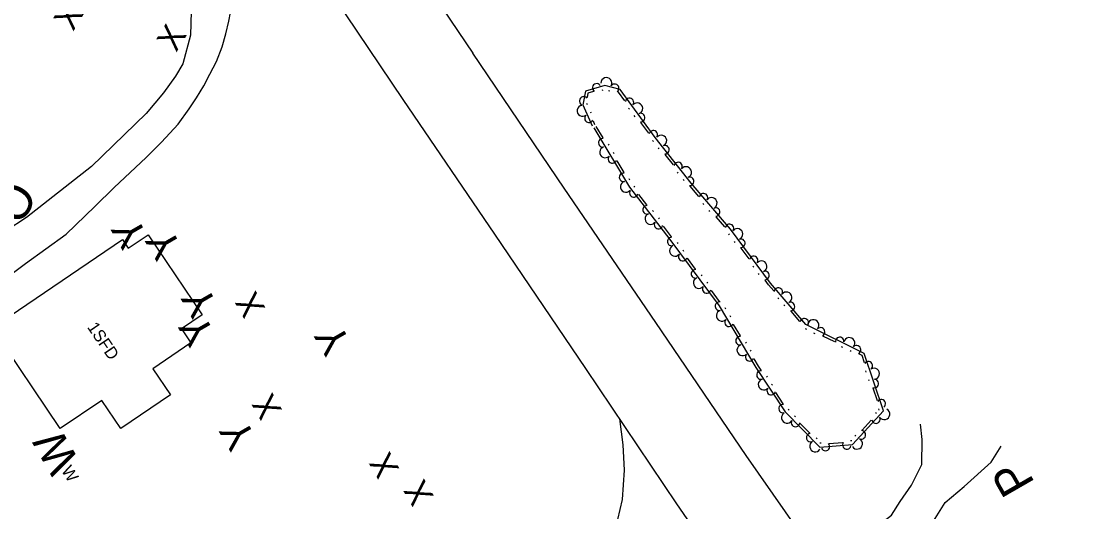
# Model space of a CAD drawing. Extents: x 2030130 to 2036320, y 723205 to 762423.
# Drawn here: x 2034222.4 to 2034546.3, y 759693.3 to 759843.4 of the extents above; entities that cross this region are included whole.
import ezdxf

# ---------------------------------------------------------------- set-up
doc = ezdxf.new("R2010")
doc.units = 0
for name, color, linetype in [('Draft_Station Cardinal Points', 7, 'Continuous'), ('Draft_Station Labels Major', 7, 'Continuous'), ('Draft_Station Tics Major', 7, 'Continuous'), ('Exist Terrain Model Ground Surface', 7, 'Continuous'), ('Old_Level_28', 7, 'Continuous'), ('Prop Horizontal Alignment Ramp', 7, 'Continuous')]:
    doc.layers.add(name, color=color, linetype=linetype)

msp = doc.modelspace()

# ---------------------------------------------------------------- linework, layer by layer
at = {"layer": 'Draft_Station Labels Major'}
for p, q in [((2034332.4, 759875.51), (2034360.74, 759833.62)), ((2034311.52, 759860.74), (2034339.29, 759819.51))]:
    msp.add_line(p, q, dxfattribs=at)
for points in [[(2034177, 759721.53), (2034180.72, 759730), (2034182.43, 759733.06), (2034184.49, 759735.91), (2034187.7, 759739.54), (2034191.49, 759743.09), (2034202.52, 759753.47), (2034223.72, 759769.25), (2034236.14, 759778.23), (2034244.9, 759786.68), (2034250.83, 759792.5), (2034255.75, 759797.17), (2034260.67, 759801.7), (2034265.36, 759806.38), (2034270.5, 759811.9), (2034273.88, 759816.63), (2034276.11, 759819.93), (2034278.35, 759823.61), (2034280.21, 759827.21), (2034282.23, 759831.05), (2034283.96, 759835.6), (2034285.09, 759839.52), (2034285.94, 759843.41), (2034287.05, 759848.7)], [(2034274.52, 759850.16), (2034274.27, 759839.19), (2034271.93, 759830.41), (2034269.69, 759826.59), (2034265.94, 759821.49), (2034260.7, 759815.17), (2034243.93, 759798.91), (2034223.99, 759783.37), (2034217.84, 759779.25), (2034213.65, 759777.27), (2034208.46, 759775.2), (2034203.67, 759773.55), (2034199.86, 759772.16), (2034197.07, 759771.63), (2034194.93, 759771.4)], [(2034673.1, 759374.03), (2034641.13, 759420.91), (2034612.37, 759462.99), (2034584.85, 759503.64), (2034556.5, 759545.4), (2034528.56, 759586.42), (2034500.61, 759627.72), (2034473.04, 759669.67), (2034444.47, 759710.51), (2034416.72, 759751.28), (2034388.73, 759792.32), (2034360.74, 759833.62)], [(2034339.29, 759819.51), (2034367.32, 759778.28), (2034395.22, 759737.17), (2034423.09, 759695.79), (2034451.3, 759654.89), (2034478.88, 759613.26), (2034507.24, 759572.41), (2034535.18, 759531.29), (2034563.29, 759490.2), (2034591.25, 759449.01), (2034619.59, 759406.87), (2034651.36, 759359.7)], [(2034405.64, 759721.71), (2034406.6, 759713.82), (2034407.01, 759706.02), (2034406.4, 759697.05), (2034404.29, 759687.94)], [(2034461.93, 759685.55), (2034467.45, 759684.39), (2034470.48, 759684.34), (2034473.71, 759684.94), (2034476.94, 759685.54), (2034481.54, 759687.19), (2034485.39, 759689.48), (2034488.94, 759692.26), (2034491.58, 759696.47), (2034495.1, 759701.46), (2034498.26, 759707.8), (2034498.3, 759715.39), (2034497.82, 759720.13)], [(2034487.48, 759647.7), (2034485.78, 759656.85), (2034486.54, 759661.62), (2034488.93, 759667.03), (2034491.55, 759672.71), (2034496.14, 759679.63), (2034499.28, 759686.35), (2034505.38, 759696.13), (2034511.18, 759701.05), (2034519.44, 759708.47), (2034522.54, 759713.39)]]:
    msp.add_lwpolyline(points, dxfattribs=at)
at = {"layer": 'Draft_Station Tics Major'}
for points in [[(2034397.73, 759810.77), (2034408.7, 759792.6), (2034421.07, 759776.67), (2034436.15, 759756.32), (2034447.41, 759737.48), (2034456.37, 759723.85), (2034466.95, 759713.13), (2034477.01, 759713.94), (2034486.52, 759724.21), (2034480.57, 759741.76), (2034462.71, 759750.6), (2034451.91, 759763.31), (2034439.58, 759779.74), (2034427.57, 759793.85), (2034416.59, 759807.85), (2034405.79, 759822.47), (2034401.1, 759823.76), (2034395.24, 759821.99), (2034394.43, 759817.86), (2034397.26, 759811.45)], [(2034397.7, 759821.88), (2034395.95, 759821.35), (2034395.71, 759820.08)], [(2034400.57, 759822.31), (2034400.18, 759822.19)], [(2034402.65, 759822.05), (2034402.26, 759822.16)], [(2034407.29, 759819.05), (2034405.29, 759821.75), (2034405.13, 759821.8)], [(2034395.57, 759818.33), (2034395.74, 759817.95)], [(2034396.73, 759815.7), (2034396.9, 759815.33)], [(2034408.67, 759816.49), (2034408.43, 759816.82)], [(2034397.52, 759812.91), (2034398.01, 759811.78)], [(2034410.38, 759814.19), (2034410.13, 759814.52)], [(2034414.61, 759809.15), (2034412.17, 759812.45)], [(2034398.43, 759811.2), (2034400.55, 759807.69)], [(2034402.17, 759805.79), (2034402.38, 759805.44)], [(2034416.02, 759806.58), (2034415.76, 759806.91)], [(2034403.66, 759803.33), (2034403.87, 759802.98)], [(2034417.79, 759804.32), (2034417.54, 759804.65)], [(2034422.16, 759799.42), (2034419.63, 759802.64)], [(2034404.79, 759800.67), (2034406.91, 759797.15)], [(2034423.61, 759796.9), (2034423.36, 759797.22)], [(2034408.53, 759795.26), (2034408.74, 759794.91)], [(2034409.98, 759792.95), (2034410.23, 759792.63)], [(2034425.39, 759794.64), (2034425.13, 759794.97)], [(2034429.92, 759789.83), (2034427.26, 759792.95)], [(2034411.42, 759790.44), (2034413.93, 759787.2)], [(2034431.47, 759787.37), (2034431.2, 759787.69)], [(2034415.77, 759785.51), (2034416.02, 759785.18)], [(2034417.53, 759783.24), (2034417.78, 759782.91)], [(2034433.33, 759785.19), (2034433.06, 759785.5)], [(2034437.89, 759780.45), (2034435.23, 759783.58)], [(2034418.97, 759780.72), (2034421.48, 759777.48)], [(2034439.33, 759778.02), (2034439.09, 759778.34)], [(2034423.3, 759775.74), (2034423.54, 759775.41)], [(2034425, 759773.43), (2034425.25, 759773.1)], [(2034441.06, 759775.72), (2034440.81, 759776.05)], [(2034445.32, 759770.72), (2034442.86, 759774)], [(2034426.38, 759770.88), (2034428.83, 759767.59)], [(2034446.72, 759768.18), (2034446.47, 759768.5)], [(2034430.62, 759765.86), (2034430.86, 759765.53)], [(2034448.45, 759765.88), (2034448.2, 759766.21)], [(2034452.86, 759760.93), (2034451.27, 759762.8), (2034450.25, 759764.16)], [(2034432.33, 759763.55), (2034432.57, 759763.22)], [(2034433.71, 759761), (2034436.15, 759757.7)], [(2034454.4, 759758.48), (2034454.14, 759758.79)], [(2034437.9, 759755.79), (2034438.11, 759755.44)], [(2034456.26, 759756.29), (2034456, 759756.6)], [(2034460.82, 759751.56), (2034458.17, 759754.68)], [(2034439.38, 759753.33), (2034439.59, 759752.98)], [(2034440.49, 759750.66), (2034442.6, 759747.13)], [(2034462.99, 759749.09), (2034462.62, 759749.27)], [(2034465.56, 759747.81), (2034465.19, 759748)], [(2034444.21, 759745.23), (2034444.42, 759744.88)], [(2034471.62, 759745.27), (2034467.95, 759747.09)], [(2034445.68, 759742.77), (2034445.89, 759742.42)], [(2034474.02, 759743.63), (2034473.65, 759743.81)], [(2034476.59, 759742.36), (2034476.22, 759742.54)], [(2034480.67, 759738.91), (2034479.9, 759741.17), (2034478.97, 759741.63)], [(2034446.8, 759740.09), (2034448.1, 759737.92), (2034448.95, 759736.64)], [(2034450.64, 759734.81), (2034450.86, 759734.46)], [(2034481.2, 759736.06), (2034481.07, 759736.45)], [(2034452.22, 759732.41), (2034452.44, 759732.07)], [(2034482.13, 759733.34), (2034481.99, 759733.73)], [(2034453.45, 759729.78), (2034455.7, 759726.36)], [(2034484.62, 759727.26), (2034483.3, 759731.14)], [(2034457.25, 759724.71), (2034457.54, 759724.42)], [(2034485.16, 759724.41), (2034485.03, 759724.8)], [(2034459.26, 759722.67), (2034459.55, 759722.38)], [(2034484.1, 759723.4), (2034484.37, 759723.7)], [(2034460.99, 759720.34), (2034463.87, 759717.42)], [(2034479.94, 759718.31), (2034482.72, 759721.32)], [(2034465.89, 759715.96), (2034466.18, 759715.67)], [(2034476.37, 759715.12), (2034476.78, 759715.15)], [(2034477.69, 759716.48), (2034477.97, 759716.78)], [(2034466.97, 759714.37), (2034467.37, 759714.4)], [(2034469.86, 759714.19), (2034473.95, 759714.52)]]:
    msp.add_lwpolyline(points, dxfattribs=at)
for centre, radius, start, end in [((2034401.61, 759824.47), 1.69, 330.6196, 178.6921), ((2034398.64, 759823.02), 1.3, 35.2285, 236.025), ((2034404.16, 759822.91), 1.3, 305.4244, 146.2209), ((2034394.66, 759819.04), 1.3, 39.6513, 240.4479), ((2034408.69, 759818.55), 1.3, 324.8923, 165.6888), ((2034394.36, 759816), 1.69, 99.7751, 307.8476), ((2034411.05, 759816.72), 1.69, 292.4211, 140.4935), ((2034396.27, 759813.7), 1.3, 132.2463, 333.0429), ((2034412.1, 759813.93), 1.3, 267.2258, 108.0224), ((2034416, 759808.65), 1.3, 324.8923, 165.6888), ((2034400.48, 759806.21), 1.3, 81.8856, 282.6822), ((2034418.39, 759806.88), 1.69, 294.086, 142.1585), ((2034401.26, 759803.33), 1.69, 107.0809, 315.1534), ((2034419.52, 759804.12), 1.3, 268.8907, 109.6873), ((2034403.45, 759801.29), 1.3, 139.5521, 340.3487), ((2034423.57, 759798.95), 1.3, 326.5572, 167.3537), ((2034406.84, 759795.68), 1.3, 81.8856, 282.6822), ((2034425.99, 759797.2), 1.69, 294.086, 142.1585), ((2034407.62, 759792.8), 1.69, 107.0809, 315.1534), ((2034427.11, 759794.44), 1.3, 268.8907, 109.6873), ((2034410.02, 759790.9), 1.3, 146.2774, 347.074), ((2034431.34, 759789.42), 1.3, 328.8247, 169.6213), ((2034414.04, 759785.72), 1.3, 88.611, 289.4075), ((2034433.83, 759787.77), 1.69, 296.3535, 144.426), ((2034435.06, 759785.05), 1.3, 271.1582, 111.9548), ((2034415.15, 759782.95), 1.69, 113.8062, 321.8787), ((2034417.56, 759781.19), 1.3, 146.2774, 347.074), ((2034439.31, 759780.05), 1.3, 328.8247, 169.6213), ((2034441.71, 759778.26), 1.69, 292.8597, 140.9322), ((2034421.57, 759776), 1.3, 87.3119, 288.1084), ((2034442.78, 759775.47), 1.3, 267.6645, 108.461), ((2034422.62, 759773.2), 1.69, 112.5071, 320.5796), ((2034424.99, 759771.38), 1.3, 144.9783, 345.7749), ((2034446.72, 759770.23), 1.3, 325.3309, 166.1275), ((2034449.1, 759768.42), 1.69, 292.8597, 140.9322), ((2034428.9, 759766.11), 1.3, 87.3119, 288.1084), ((2034450.17, 759765.63), 1.3, 267.6645, 108.461), ((2034429.95, 759763.32), 1.69, 112.5071, 320.5796), ((2034432.32, 759761.5), 1.3, 144.9783, 345.7749), ((2034454.28, 759760.52), 1.3, 328.785, 169.5816), ((2034456.76, 759758.87), 1.69, 296.3138, 144.3863), ((2034436.22, 759756.22), 1.3, 81.6206, 282.4172), ((2034458, 759756.15), 1.3, 271.1185, 111.9151), ((2034436.98, 759753.33), 1.69, 106.8159, 314.8884), ((2034439.16, 759751.29), 1.3, 139.2871, 340.0836), ((2034462.24, 759751.15), 1.3, 328.785, 169.5816), ((2034465, 759750.38), 1.69, 319.6223, 167.6948), ((2034467.21, 759748.37), 1.3, 294.427, 135.2236), ((2034442.52, 759745.66), 1.3, 81.6206, 282.4172), ((2034443.29, 759742.77), 1.69, 106.8159, 314.8884), ((2034473.09, 759745.46), 1.3, 352.0935, 192.8901), ((2034476.03, 759744.92), 1.69, 319.6223, 167.6948), ((2034478.24, 759742.91), 1.3, 294.427, 135.2236), ((2034445.47, 759740.73), 1.3, 139.2871, 340.0836), ((2034481.84, 759738.01), 1.3, 307.1907, 147.9872), ((2034448.94, 759735.16), 1.3, 84.0927, 284.8892), ((2034483.54, 759735.55), 1.69, 274.7195, 122.792), ((2034449.83, 759732.31), 1.69, 109.2879, 317.3604), ((2034483.69, 759732.57), 1.3, 249.5242, 90.3208), ((2034452.09, 759730.36), 1.3, 141.7591, 342.5557), ((2034455.69, 759724.88), 1.3, 84.0927, 284.8892), ((2034485.8, 759726.36), 1.3, 307.1907, 147.9872), ((2034486.72, 759723.21), 1.69, 213.1641, 61.2366), ((2034456.94, 759722.11), 1.69, 120.6018, 328.6743), ((2034484.16, 759721.66), 1.3, 187.9688, 28.7654), ((2034459.54, 759720.64), 1.3, 153.073, 353.8695), ((2034464.15, 759715.97), 1.3, 95.4065, 296.2031), ((2034478.36, 759714.18), 1.69, 213.1641, 61.2366), ((2034479.7, 759716.85), 1.3, 245.6353, 86.4318), ((2034465.58, 759713.35), 1.69, 120.6018, 328.6743), ((2034468.7, 759713.27), 1.3, 202.9948, 43.7913), ((2034475.24, 759713.79), 1.3, 145.3283, 346.1249)]:
    msp.add_arc(centre, radius, start, end, dxfattribs=at)
at = {"layer": 'Exist Terrain Model Ground Surface'}
msp.add_lwpolyline([(2034213.49, 759749.58), (2034253.37, 759776.62), (2034255.17, 759773.96), (2034261.24, 759778.08), (2034277.84, 759753.61), (2034271.45, 759749.28), (2034274.37, 759744.97), (2034262.72, 759737.07), (2034268.13, 759729.08), (2034252.94, 759718.77), (2034247.08, 759727.4), (2034234.37, 759718.78)], close=True, dxfattribs=at)

# ---------------------------------------------------------------- texts
at = {"layer": 'Draft_Station Cardinal Points'}
msp.add_text('O', height=10.66, rotation=58.9267, dxfattribs=at).set_placement((2034222.04, 759780.56))
at = {"layer": 'Draft_Station Tics Major'}
for s, height, rotation, p in [('X', 7.38, 58.9267, (2034238.28, 759840.13)), ('X', 7.38, 58.9267, (2034269.85, 759833.72)), ('Y', 9.02, 119.9336, (2034261.45, 759777.37)), ('Y', 9.02, 119.9336, (2034271.89, 759773.93)), ('X', 7.38, 119.9336, (2034297.3, 759755.59)), ('Y', 9.02, 119.9336, (2034282.88, 759756.28)), ('Y', 9.02, 119.9336, (2034282.04, 759747.51)), ('Y', 9.02, 119.9336, (2034323.66, 759744.73)), ('X', 7.38, 119.9336, (2034302.42, 759724.4)), ('Y', 9.02, 119.9336, (2034294.57, 759715.66)), ('X', 7.38, 119.9336, (2034338.33, 759706.42)), ('X', 7.38, 119.9336, (2034348.9, 759698.02))]:
    msp.add_text(s, height=height, rotation=rotation, dxfattribs=at).set_placement(p)
at = {"layer": 'Exist Terrain Model Ground Surface'}
msp.add_text('W', height=9.84, rotation=119.9336, dxfattribs=at).set_placement((2034240.4, 759708.67))
at = {"layer": 'Old_Level_28'}
for s, height, rotation, p in [('1SFD', 3.691, 304.1378, (2034242.47, 759749.81)), ('W', 3.69, 302.2562, (2034234.55, 759705.96))]:
    msp.add_text(s, height=height, rotation=rotation, dxfattribs=at).set_placement(p)
at = {"layer": 'Prop Horizontal Alignment Ramp'}
msp.add_text('P', height=10.66, rotation=119.9336, dxfattribs=at).set_placement((2034532.99, 759702.08))

doc.saveas('drawing.dxf')
